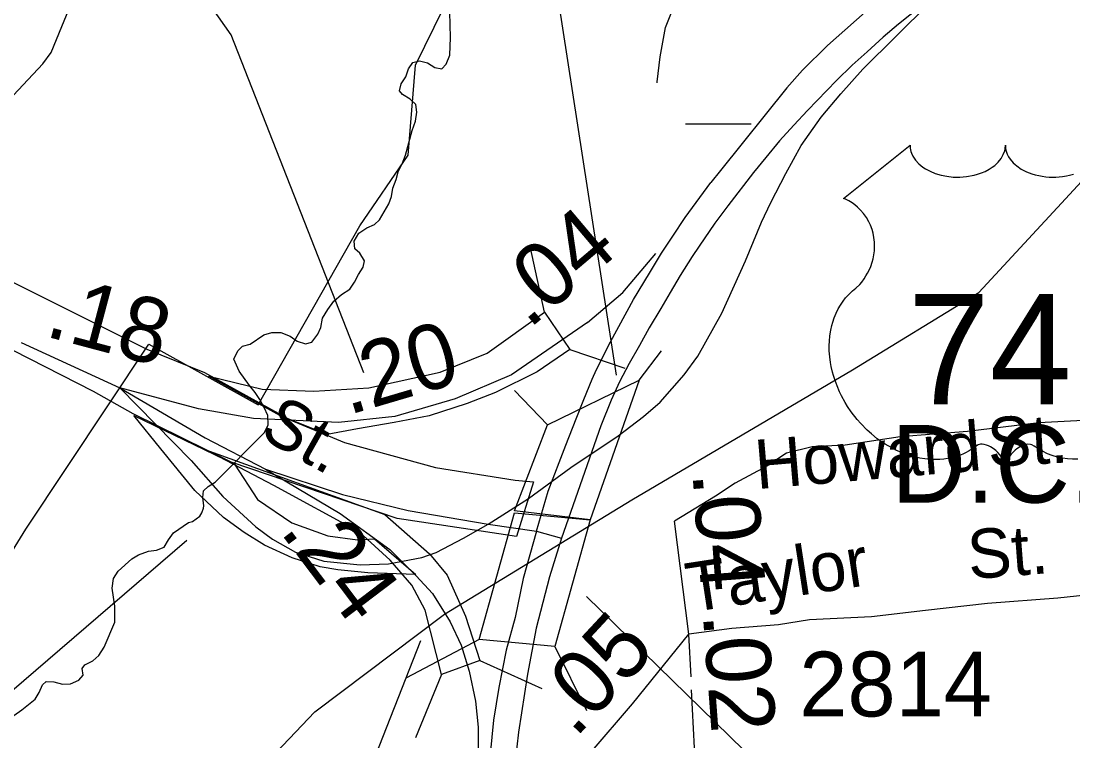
# Model space of a CAD drawing. Extents: x 2290055 to 2389491, y 66597 to 237875.
# Drawn here: x 2317120 to 2319151, y 183566 to 184954 of the extents above; entities that cross this region are included whole.
import ezdxf

# ---------------------------------------------------------------- set-up
doc = ezdxf.new("R2010")
doc.units = 0
for name, color, linetype in [('Exist Boundary Political City Limit New', 7, 'Continuous'), ('Exist Cultural Educational Facility Middle Label', 7, 'Continuous'), ('Exist Hydrographic Buffer Line', 7, 'Continuous'), ('Exist Hydrographic River Shore', 7, 'Continuous'), ('Exist Railroad Mainline', 7, 'Continuous'), ('Exist Road Non-System Type 51', 7, 'Continuous'), ('Exist Road Non-System Type 51 Label', 7, 'Continuous'), ('Exist Road Primary US Attributed', 7, 'Continuous'), ('Exist Road Primary US Divided Attributed', 7, 'Continuous'), ('Exist Road Primary US Label', 7, 'Continuous'), ('Exist Road Primary US Mileage Hundredths English Label', 7, 'Continuous'), ('Exist Road Primary US Ramp 1 Lane  Attributed', 7, 'Continuous'), ('Exist Road Primary US Shield CELL', 7, 'Continuous'), ('Exist Road Primary US Shield Number Label', 7, 'Continuous'), ('Exist Road Primary US Structure Ovrhead Sign CELL', 7, 'Continuous'), ('Exist Road Primary US Structure Standard Bridge CELL', 7, 'Continuous'), ('Exist Road Primary US Structure Standard Bridge Number Label', 7, 'Continuous'), ('Exist Road Secondary Mileage Hundredths English Label', 7, 'Continuous'), ('Exist Road Secondary Type 51 Attributed', 7, 'Continuous'), ('Exist Road Secondary Type 51 Divided Attributed', 7, 'Continuous'), ('Exist Road Secondary Type 51 Number Label', 7, 'Continuous'), ('Map Preparation Boundary City Limit Buffer Line', 7, 'Continuous')]:
    doc.layers.add(name, color=color, linetype=linetype)

msp = doc.modelspace()

# ---------------------------------------------------------------- linework, layer by layer
at = {"layer": 'Exist Boundary Political City Limit New'}
msp.add_lwpolyline([(2316416.5, 181436.2), (2316467, 181809.6), (2316532.5, 182051.8), (2316633.2, 182410.1), (2316693.8, 182647.2), (2316865.2, 183283), (2316995.5, 183732.8), (2317061.8, 183852.7), (2317086.5, 183904.3), (2317129.8, 183974.6), (2317367, 184331.3), (2317578, 184214.4), (2317774.2, 184559.5), (2317867.2, 184695.9), (2317881.8, 184869.5), (2317954, 185016.3)], dxfattribs=at)
at = {"layer": 'Exist Hydrographic Buffer Line'}
msp.add_lwpolyline([(2316402.6, 184061.9), (2317162.2, 184871.8), (2317178.6, 184893.9), (2317396.7, 185425.6)], dxfattribs=at)
at = {"layer": 'Exist Hydrographic River Shore'}
for points in [[(2317590, 184160.8), (2317597.2, 184175.3), (2317596.5, 184193.5), (2317589.7, 184209.2), (2317581, 184224.3), (2317572, 184238.2), (2317561.5, 184251.4), (2317541.5, 184279), (2317531.2, 184302.1), (2317539, 184318.6), (2317547.7, 184327.5), (2317562.5, 184331.1), (2317589, 184348.9), (2317604.7, 184353.7), (2317621.7, 184353.7), (2317639.5, 184346.8), (2317653, 184337.1), (2317669.5, 184331.5), (2317681.5, 184335), (2317693, 184350.3), (2317699.2, 184363.6), (2317702.2, 184381.1), (2317712.7, 184398.2), (2317724.2, 184413.9), (2317738.7, 184427), (2317754.7, 184437.1), (2317764, 184450.5), (2317771.7, 184465.7), (2317780.5, 184479.8), (2317783.5, 184492), (2317774.5, 184506.7), (2317764.5, 184514.9), (2317763, 184529.9), (2317772.2, 184545.1), (2317787.5, 184555.5), (2317802.7, 184562.1), (2317812.2, 184570.8), (2317830.2, 184601.9), (2317835.2, 184616.2), (2317838.2, 184632), (2317844.2, 184648.8), (2317848, 184663.4), (2317856, 184678.7), (2317862.5, 184695.8), (2317875, 184743.6), (2317881.5, 184761.1), (2317884.5, 184778.6), (2317882.5, 184793.4), (2317871.7, 184804), (2317856.7, 184813), (2317851, 184819.6), (2317853.7, 184833.4), (2317863, 184846.8), (2317868, 184862.1), (2317876.7, 184874.2), (2317889.7, 184877.8), (2317905, 184873.7), (2317919.2, 184864.6), (2317932.5, 184862), (2317940.7, 184871), (2317947.7, 184888.4), (2317949, 184923), (2317948, 184971.3)], [(2317472.3, 184014.9), (2317473, 184019.2), (2317471, 184035.4), (2317472.5, 184048.3), (2317481.5, 184056.8), (2317495, 184064.8), (2317590, 184160.8)], [(2317147.5, 183646.1), (2317155.5, 183659.4), (2317161.5, 183674), (2317168.5, 183680.7), (2317183.5, 183679.8), (2317200.5, 183675.3), (2317216, 183675.8), (2317231.7, 183683), (2317240.5, 183692.9), (2317238.5, 183705.6), (2317243.5, 183712.9), (2317259, 183720.5), (2317270.7, 183730.7), (2317280.5, 183746.7), (2317301.5, 183794.6), (2317301.2, 183825.8), (2317296.2, 183860.4), (2317299, 183879.1), (2317308, 183893.3), (2317334.2, 183916.9), (2317347, 183924.9), (2317366.5, 183931.8), (2317381.7, 183933.5), (2317396.7, 183939.4), (2317405.2, 183953.7), (2317414.5, 183966.9), (2317443.5, 183987), (2317451.5, 183989), (2317465.1, 183999.5), (2317469.2, 184006.1), (2317472.3, 184014.9)], [(2317106.2, 183614.7), (2317121.7, 183625.6), (2317147.5, 183646.1)]]:
    msp.add_lwpolyline(points, dxfattribs=at)
at = {"layer": 'Exist Railroad Mainline'}
msp.add_lwpolyline([(2317368.7, 183162.4), (2317386.6, 183219.3), (2317454.9, 183335.6), (2317526.4, 183452.7), (2317687.4, 183621.9), (2317937.9, 183810.5), (2318299, 184030.9), (2318725.1, 184281.4), (2318969.1, 184431), (2319128.4, 184603.4), (2319252, 184736.8), (2319359.4, 184941.7), (2319414.7, 185094.6), (2319460.2, 185262.1), (2319475, 185682.8)], dxfattribs=at)
at = {"layer": 'Exist Road Non-System Type 51'}
for points in [[(2319182.6, 184184.8), (2319084.6, 184179.1), (2318946.8, 184162.6), (2318817, 184152.3), (2318711.2, 184136.5), (2318647.3, 184133.3), (2318597.6, 184120.6), (2318559.9, 184095.9), (2318498.4, 184062.8), (2318461, 184038.1), (2318381.3, 183989.4)], [(2319217.4, 183851.6), (2319121.6, 183841.4), (2318985.8, 183831), (2318865.9, 183817.1), (2318762.1, 183805.1), (2318642.3, 183799.2), (2318582.4, 183790), (2318492.5, 183782.6), (2318409.4, 183771.5)], [(2318442.2, 183345.1), (2318420.2, 183552.3), (2318414.7, 183664.6)]]:
    msp.add_lwpolyline(points, dxfattribs=at)
at = {"layer": 'Exist Road Primary US Attributed'}
msp.add_lwpolyline([(2317120.3, 184334.3), (2317310.7, 184246.6)], dxfattribs=at)
at = {"layer": 'Exist Road Primary US Divided Attributed'}
for points in [[(2318876.6, 184998.9), (2318814.1, 184948.5), (2318784.2, 184923.2), (2318753.3, 184895.2), (2318724.7, 184869.2), (2318694.5, 184839.9), (2318638.3, 184782), (2318612.1, 184753.6), (2318584.4, 184723.1), (2318558.1, 184691.1), (2318534, 184662.4), (2318484.6, 184598), (2318459.3, 184564.5), (2318429, 184519.9), (2318415.4, 184500.1), (2318392.2, 184463.8), (2318373, 184430.9), (2318355, 184399.8), (2318333, 184362.8), (2318313.8, 184328.7), (2318294.3, 184293.9), (2318275.6, 184258.2), (2318259.5, 184223.1), (2318239.5, 184173.8), (2318163.6, 183956.9)], [(2318766.5, 184986.1), (2318676.8, 184907.3), (2318628.9, 184859.5), (2318598.1, 184825.9), (2318470.4, 184665.9), (2318451.4, 184642.9)], [(2318115.1, 183970.3), (2318137.8, 184047.8), (2318171.9, 184136.6), (2318191.5, 184186.8), (2318206.7, 184224.4), (2318222.9, 184263.7), (2318231.3, 184282.3), (2318258.3, 184335.7), (2318302.5, 184417.6), (2318333.5, 184468.2), (2318356.8, 184506.5), (2318378.1, 184539.2), (2318402.2, 184575.5), (2318451.4, 184642.9)], [(2318213.5, 184372.9), (2318281.8, 184430.7), (2318345.8, 184505.8)], [(2318213.5, 184372.9), (2318066.7, 184271.8), (2317958, 184226), (2317841.7, 184191.7), (2317733, 184180.2), (2317569, 184187.9), (2317463, 184206.2), (2317310.7, 184246.6)], [(2317310.7, 184246.6), (2317475.5, 184150.2), (2317592.1, 184090)], [(2317592.1, 184090), (2317740.6, 184041), (2317867.3, 184010.6), (2318021.7, 183983.7), (2318115.1, 183970.3), (2318163.6, 183956.9)], [(2317592.1, 184090), (2317736, 184004.3), (2317832.2, 183935.2), (2317882.8, 183884.5), (2317914.8, 183850.4), (2317948.9, 183795.7), (2317969.5, 183750.2), (2317985, 183700.6), (2317997.4, 183642.8), (2318002.6, 183592.2), (2318002.6, 183529.2), (2318002.6, 183432.1), (2318020.9, 183338.1)]]:
    msp.add_lwpolyline(points, dxfattribs=at)
at = {"layer": 'Exist Road Primary US Ramp 1 Lane  Attributed'}
msp.add_lwpolyline([(2317310.7, 184246.6), (2317448.6, 184106.6), (2317509.5, 184037.4), (2317573.6, 183978.5), (2317605.6, 183954.8), (2317650, 183930), (2317704.7, 183912.4), (2317774.9, 183905.2), (2317829.6, 183907.3), (2317893.6, 183919.7), (2317921.5, 183929), (2317974.2, 183956.9), (2318021.7, 183983.7), (2318100.1, 184033.3), (2318181.2, 184093.2), (2318273.1, 184154.2), (2318321.6, 184191.4), (2318353.6, 184219.3), (2318400.1, 184271.9), (2318426.4, 184308.1), (2318472.9, 184390.7), (2318518.3, 184492), (2318549.3, 184566.4), (2318567.4, 184604.6), (2318596.3, 184660.4), (2318626.2, 184714.1), (2318664.4, 184768.8), (2318702.6, 184814.3), (2318745, 184861.8), (2318873.5, 184988.9)], dxfattribs=at)
at = {"layer": 'Exist Road Primary US Shield CELL'}
msp.add_lwpolyline([(2319160.1, 184109.1), (2319150, 184109.1), (2319140.1, 184109.8), (2319130.7, 184111.2), (2319120.9, 184113.2), (2319110.6, 184116.3), (2319101.3, 184119.9), (2319091.9, 184124.6), (2319076, 184134.6), (2319071.4, 184137), (2319068.8, 184137.7), (2319062.7, 184138), (2319056.9, 184136.8), (2319051, 184134.4), (2319047.4, 184132.5), (2319042.6, 184129.4), (2319039, 184126.5), (2319034.6, 184122.4), (2319031.6, 184118.9), (2319029.2, 184116.1), (2319024.8, 184109.1), (2319023.2, 184105.7), (2319021.5, 184101.4), (2319020, 184095), (2319018, 184103.1), (2319015.6, 184108.4), (2319012.9, 184112.9), (2319010.1, 184117), (2319005.6, 184122.1), (2319001.6, 184126), (2318996.7, 184130), (2318991.5, 184133.1), (2318987.4, 184135.2), (2318983.6, 184136.6), (2318979, 184137.8), (2318975.2, 184138.1), (2318972.1, 184138), (2318967.8, 184137), (2318962, 184132.8), (2318956.4, 184129), (2318950.4, 184125.3), (2318943.3, 184121.5), (2318938.1, 184119.1), (2318931.8, 184116.7), (2318924.5, 184114.2), (2318916.7, 184112.2), (2318908.5, 184110.6), (2318901.4, 184109.4), (2318893.7, 184108.8), (2318886.8, 184108.5), (2318879.6, 184108.6), (2318872.8, 184109.1), (2318865, 184109.8), (2318855.3, 184111.3), (2318847.2, 184113.1), (2318838.7, 184115.4), (2318830, 184118.1), (2318820.7, 184121.7), (2318809, 184126.8), (2318800.8, 184130.9), (2318788, 184138.3), (2318773, 184148.7), (2318761.6, 184157.9), (2318753.3, 184165.4), (2318741.1, 184177.9), (2318733.9, 184186), (2318722.6, 184200.6), (2318715.4, 184211.2), (2318710.7, 184218.9), (2318703.9, 184231.4), (2318700.1, 184239.2), (2318695.3, 184250.6), (2318691.4, 184261), (2318688.2, 184270.9), (2318686.5, 184277.2), (2318684.1, 184288.2), (2318682.6, 184296.1), (2318681.2, 184306.8), (2318680.4, 184318.1), (2318680.2, 184328.5), (2318680.5, 184337.2), (2318681.5, 184347.3), (2318683.2, 184358), (2318685.2, 184367.2), (2318687.1, 184373.8), (2318689.8, 184381.9), (2318693.4, 184390.7), (2318697.7, 184399.3), (2318701.8, 184406.3), (2318706.9, 184413.9), (2318711.9, 184420.4), (2318718.4, 184427.5), (2318725.3, 184434.1), (2318731.5, 184439.2), (2318739, 184446.4), (2318742.9, 184450.9), (2318747.5, 184457), (2318751.2, 184462.7), (2318754.2, 184467.8), (2318758.1, 184475.3), (2318760.5, 184480.9), (2318763.4, 184489.6), (2318764.9, 184495.7), (2318766.4, 184503.5), (2318767.4, 184510.9), (2318767.8, 184520.1), (2318767.6, 184527.7), (2318766.6, 184536.6), (2318764.9, 184545.1), (2318762.9, 184552.5), (2318759.7, 184561), (2318756.8, 184567.3), (2318751.9, 184575.7), (2318746.4, 184583.5), (2318740.7, 184589.9), (2318735, 184595.6), (2318729.6, 184599.9), (2318724.4, 184603.6), (2318717.8, 184607.5), (2318711.5, 184610.7), (2318707.6, 184612.2), (2318836.2, 184714.7), (2318836.5, 184709.4), (2318837.8, 184703.1), (2318838.8, 184699.8), (2318841.7, 184693.6), (2318846.6, 184686.2), (2318853.4, 184679), (2318861.1, 184672.7), (2318866.2, 184669.3), (2318875, 184664.6), (2318884.9, 184660.4), (2318896, 184657.2), (2318907.3, 184655), (2318919.7, 184653.6), (2318932, 184653.4), (2318945.2, 184654.3), (2318959.8, 184657.2), (2318966.5, 184658.9), (2318974, 184661.5), (2318981, 184664.4), (2318988.7, 184668.5), (2318994.8, 184672.4), (2318999.7, 184675.9), (2319006.5, 184682.5), (2319011.9, 184689.2), (2319014.2, 184693), (2319016.2, 184696.7), (2319018.9, 184704.4), (2319019.6, 184707.8), (2319020.2, 184715), (2319020.6, 184709), (2319021.2, 184705.3), (2319022.2, 184701.6), (2319023.7, 184697.7), (2319026.5, 184692.3), (2319029.5, 184687.7), (2319035.2, 184680.9), (2319038.8, 184677.6), (2319042.1, 184674.9), (2319050.8, 184668.9), (2319061, 184663.8), (2319066, 184661.6), (2319071.2, 184659.7), (2319077.7, 184657.8), (2319084.5, 184656.2), (2319091.2, 184655), (2319098, 184654), (2319105, 184653.5), (2319110.7, 184653.4), (2319117.7, 184653.4), (2319124.1, 184653.8), (2319130.7, 184654.6), (2319138, 184655.8), (2319143.9, 184657.1), (2319151.6, 184659.1)], dxfattribs=at)
at = {"layer": 'Exist Road Primary US Structure Ovrhead Sign CELL'}
msp.add_line((2318402.8, 184756.4), (2318529.3, 184756.4), dxfattribs=at)
at = {"layer": 'Exist Road Primary US Structure Standard Bridge CELL'}
for p, q in [((2316894.2, 184555.8), (2317363.1, 184321.4)), ((2318130.8, 184392.8), (2318103.6, 184517.2)), ((2317260, 184239.9), (2316954.2, 184395.2)), ((2318019.7, 184314), (2318130.8, 184392.8)), ((2318130.8, 184392.8), (2318179.3, 184320.6)), ((2317363.1, 184321.4), (2317474.1, 184276.6)), ((2318179.3, 184320.6), (2318116.3, 184278.1)), ((2318179.3, 184320.6), (2318286, 184284.9)), ((2318313.7, 184261.8), (2318356.7, 184318.2)), ((2317929.2, 184277.3), (2318019.7, 184314)), ((2317474.1, 184276.6), (2317640.8, 184184.6)), ((2317791.9, 184246.8), (2317929.2, 184277.3)), ((2318116.3, 184278.1), (2318036.4, 184237.8)), ((2317482.9, 184269.2), (2317585.9, 184244.3)), ((2318136.6, 184175.7), (2318313.7, 184261.8)), ((2318313.7, 184261.8), (2318218.9, 183992.4)), ((2317337, 184196.5), (2317260, 184239.9)), ((2317585.9, 184244.3), (2317685.3, 184240.4)), ((2317685.3, 184240.4), (2317791.9, 184246.8)), ((2318036.4, 184237.8), (2317981.3, 184216.5)), ((2318136.6, 184175.7), (2318072.7, 184241.6)), ((2317981.3, 184216.5), (2317907.8, 184193.2)), ((2317525.6, 184103.3), (2317337, 184196.5)), ((2317390.4, 184129.2), (2317337.9, 184193.4)), ((2317337.9, 184193.4), (2317532.3, 184099.5)), ((2317640.8, 184184.6), (2317744.8, 184141.7)), ((2317840.8, 184180.1), (2317769.6, 184167.7)), ((2317907.8, 184193.2), (2317840.8, 184180.1)), ((2318073, 184009.9), (2318136.6, 184175.7)), ((2317769.6, 184167.7), (2317710.9, 184156.7)), ((2317744.8, 184141.7), (2317920.6, 184093.5)), ((2317456, 184049), (2317390.4, 184129.2)), ((2317608.5, 184058.2), (2317477.3, 184127.3)), ((2317477.3, 184127.3), (2317822.4, 184002.4)), ((2317846.5, 183994.8), (2317525.6, 184103.3)), ((2317532.3, 184099.5), (2317576.6, 184031.2)), ((2317920.6, 184093.5), (2318074.1, 184068.8)), ((2317773.9, 183968.6), (2317608.5, 184058.2)), ((2318074.1, 184068.8), (2318109.5, 184065.3)), ((2318109.5, 184065.3), (2318076.3, 183960.4)), ((2317510.8, 183997.1), (2317456, 184049)), ((2317576.6, 184031.2), (2317643.1, 183986.3)), ((2317551, 183967.6), (2317510.8, 183997.1)), ((2317822.4, 184002.4), (2317908.9, 183926.4)), ((2318076.3, 183960.4), (2317846.5, 183994.8)), ((2318004.4, 183761.7), (2318072.6, 184005.9)), ((2318072.6, 184005.9), (2318218.9, 183992.4)), ((2318218.9, 183992.4), (2318073, 184009.9)), ((2318218.9, 183992.4), (2318150.3, 183748)), ((2317643.1, 183986.3), (2317712.5, 183961.6)), ((2317590.1, 183943.2), (2317551, 183967.6)), ((2317712.5, 183961.6), (2317769.9, 183953.6)), ((2317769.9, 183953.6), (2317802.8, 183955.5)), ((2317833, 183914.3), (2317773.9, 183968.6)), ((2317802.8, 183955.5), (2317882.5, 183886.8)), ((2317643.6, 183919), (2317590.1, 183943.2)), ((2317697.8, 183901.6), (2317643.6, 183919)), ((2317874.3, 183866.4), (2317833, 183914.3)), ((2317908.9, 183926.4), (2317942.9, 183885.4)), ((2317731.5, 183895.6), (2317697.8, 183901.6)), ((2317789.7, 183890), (2317731.5, 183895.6)), ((2317882.5, 183886.8), (2317789.7, 183890)), ((2317942.9, 183885.4), (2317978.1, 183806.3)), ((2317900.5, 183818.1), (2317874.3, 183866.4)), ((2317932, 183694.2), (2317900.5, 183818.1)), ((2317978.1, 183806.3), (2318005.7, 183721.1)), ((2318004.4, 183761.7), (2317864, 183687.3)), ((2318150.3, 183748), (2318004.4, 183761.7)), ((2318150.3, 183748), (2318211.9, 183624.8)), ((2318005.7, 183721.1), (2317932, 183694.2)), ((2318005.7, 183721.1), (2318125.8, 183666.8)), ((2317932, 183694.2), (2317881.9, 183571.7))]:
    msp.add_line(p, q, dxfattribs=at)
msp.add_lwpolyline([(2317710.9, 184156.7), (2317619.9, 184193.4), (2317482.9, 184269.2)], dxfattribs=at)
at = {"layer": 'Exist Road Primary US Structure Standard Bridge Number Label'}
msp.add_line((2317440.2, 183952.2), (2316333.8, 183001), dxfattribs=at)
for points in [[(2318269.8, 184271.2), (2318110.7, 185298.6), (2318277.1, 185819.6)], [(2317781.8, 184276.1), (2317526, 184928), (2317120.3, 185503.8)], [(2318212, 183844.3), (2319123.6, 182954.4)], [(2317891.1, 183759.1), (2317462.1, 182667.6)]]:
    msp.add_lwpolyline(points, dxfattribs=at)
at = {"layer": 'Exist Road Secondary Type 51 Attributed'}
for points in [[(2318348, 184835.5), (2318348.2, 184837.5), (2318354.1, 184885.5), (2318364.3, 184941.7), (2318383.6, 184990.1), (2318408.4, 185060.5), (2318441.3, 185126.3), (2318516.2, 185230.7), (2318557, 185269.3), (2318615.9, 185326), (2318663.6, 185360), (2318702.1, 185380.4), (2318790.5, 185416.7), (2318847.2, 185446.2), (2318917.5, 185478), (2319060.4, 185543.8), (2319157.9, 185582.4), (2319225.9, 185609.6), (2319352.9, 185666.3), (2319402.8, 185686.7), (2319421.4, 185694.8), (2319453.3, 185706.6)], [(2318409.4, 183771.5), (2318381.3, 183989.4)], [(2318216, 183515.6), (2318218.5, 183542.3), (2318300.7, 183637.5), (2318409.4, 183771.5)], [(2318413.5, 183689.6), (2318409.4, 183771.5)]]:
    msp.add_lwpolyline(points, dxfattribs=at)
at = {"layer": 'Exist Road Secondary Type 51 Divided Attributed'}
for points in [[(2318115.1, 183970.3), (2318089.3, 183879.4), (2318073.8, 183804), (2318056.8, 183740.9), (2318042.3, 183668.6), (2318032, 183605.6), (2318025.8, 183540.5), (2318021.7, 183492), (2318024.1, 183437.3), (2318020.9, 183338.1)], [(2318163.6, 183956.9), (2318140.4, 183882.5), (2318114.6, 183783.3), (2318098.1, 183694.5), (2318080.5, 183582.9), (2318074.3, 183526.1), (2318071.2, 183452.7), (2318067.6, 183403.1), (2318068.7, 183362.8), (2318068.7, 183290.5), (2318070.7, 183230.6), (2318073.8, 183174.8), (2318082.6, 183062.2)]]:
    msp.add_lwpolyline(points, dxfattribs=at)
at = {"layer": 'Map Preparation Boundary City Limit Buffer Line'}
msp.add_lwpolyline([(2316416.5, 181436.2), (2316467, 181809.6), (2316532.5, 182051.8), (2316633.2, 182410.1), (2316693.8, 182647.2), (2316865.2, 183283), (2316995.5, 183732.8), (2317061.8, 183852.7), (2317086.5, 183904.3), (2317129.8, 183974.6), (2317367, 184331.3), (2317578, 184214.4), (2317774.2, 184559.5), (2317867.2, 184695.9), (2317881.8, 184869.5), (2317954, 185016.3)], dxfattribs=at)

# ---------------------------------------------------------------- texts
at = {"layer": 'Exist Cultural Educational Facility Middle Label'}
msp.add_text('D.C. Virgo', height=150, dxfattribs=at).set_placement((2318799.5, 184025.5))
at = {"layer": 'Exist Road Non-System Type 51 Label'}
for s, rotation, p in [('Howard', 4.8376, (2318540.5, 184051.4)), ('St.', 3.3305, (2318988.1, 184094.1)), ('St.', 4.3725, (2318950.7, 183877.7)), ('Taylor', 8.7152, (2318411.8, 183813.6))]:
    msp.add_text(s, height=95, rotation=rotation, dxfattribs=at).set_placement(p)
at = {"layer": 'Exist Road Primary US Label'}
msp.add_text('St.', height=95, rotation=330.6042, dxfattribs=at).set_placement((2317577.6, 184153.7))
at = {"layer": 'Exist Road Primary US Mileage Hundredths English Label'}
for s, rotation, p in [('.04', 40.2214, (2318100.2, 184358.9)), ('.18', 345.1251, (2317163.4, 184347.2)), ('.20', 16.4498, (2317751.5, 184194)), ('.24', 307.1443, (2317618.2, 183970.1))]:
    msp.add_text(s, height=125, rotation=rotation, dxfattribs=at).set_placement(p)
at = {"layer": 'Exist Road Primary US Shield Number Label'}
msp.add_text('74', height=212.5, dxfattribs=at).set_placement((2318831.9, 184215.4))
at = {"layer": 'Exist Road Secondary Mileage Hundredths English Label'}
for s, rotation, p in [('.04', 274.2247, (2318416.1, 184082.9)), ('.05', 47.1036, (2318189.9, 183569.5)), ('.02', 274.2247, (2318436.2, 183810.3))]:
    msp.add_text(s, height=125, rotation=rotation, dxfattribs=at).set_placement(p)
at = {"layer": 'Exist Road Secondary Type 51 Number Label'}
msp.add_text('2814', height=125, dxfattribs=at).set_placement((2318622.5, 183613))

doc.saveas('drawing.dxf')
